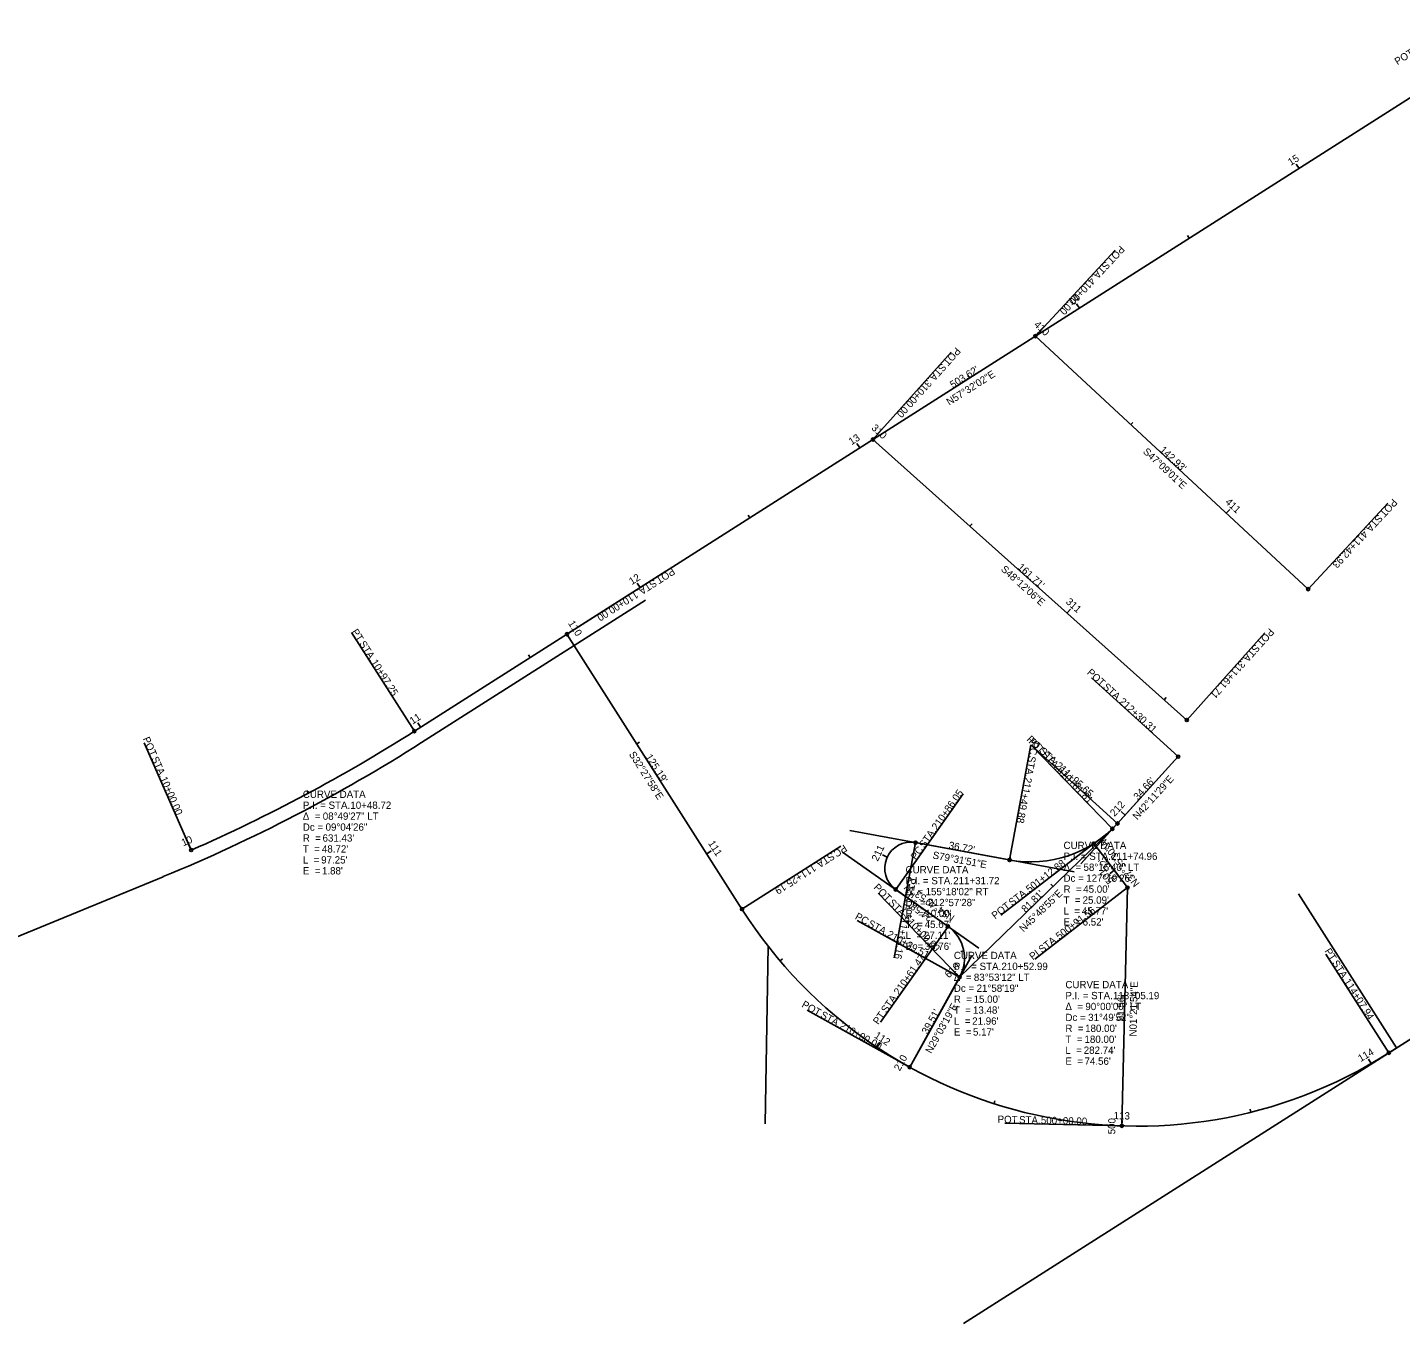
# Model space of a CAD drawing. Extents: x 143938 to 145591, y 512467 to 513276.
# Drawn here: x 144765 to 145292, y 512738 to 513236 of the extents above; entities that cross this region are included whole.
import ezdxf

# ---------------------------------------------------------------- set-up
doc = ezdxf.new("R2010")
doc.units = 0
for name, color, linetype in [('_CIVIL_CONSTRUCTION', 7, 'Continuous'), ('Default', 7, 'Continuous'), ('GE_P_Alignment', 7, 'Continuous'), ('GE_P_Alignment_100_Bearings', 7, 'Continuous'), ('GE_P_Alignment_100_Cardinal_Points', 7, 'Continuous'), ('GE_P_Alignment_100_Curve_Data', 7, 'Continuous'), ('GE_P_Alignment_100_Distances', 7, 'Continuous'), ('GE_P_Alignment_100_Stations', 7, 'Continuous'), ('GE_P_Driveway_CL', 7, 'Continuous'), ('SC_Scratch1', 7, 'Continuous')]:
    doc.layers.add(name, color=color, linetype=linetype)

msp = doc.modelspace()

# ---------------------------------------------------------------- linework, layer by layer
at = {"layer": '_CIVIL_CONSTRUCTION'}
for p, q in [((144915.99, 512961.08), (145002.01, 513015.81)), ((144609.55, 512824.24), (144816.71, 512909.56))]:
    msp.add_line(p, q, dxfattribs=at)
msp.add_arc((144574.25, 513498.21), 636.62, 292.38616, 302.46616, dxfattribs=at)
at = {"layer": 'Default'}
msp.add_line((145252.8, 512902.91), (145290.44, 512843.75), dxfattribs=at)
at = {"layer": 'GE_P_Alignment'}
for p, q in [((144913.21, 512965.47), (145338.11, 513235.81)), ((145151.72, 513117.22), (145256.51, 513020.01)), ((145089.33, 513077.52), (145209.88, 512969.74)), ((145124.06, 512737.89), (145591.23, 513035.12)), ((144971.8, 513002.75), (145039.01, 512897.12)), ((144971.8, 513002.75), (145039.01, 512897.12)), ((145183.29, 512930), (145206.56, 512955.68)), ((145122.64, 512870.94), (145181.31, 512927.96)), ((145105.66, 512922.65), (145141.77, 512915.97)), ((145105.66, 512922.65), (145141.77, 512915.97)), ((145187.13, 512905.37), (145174.13, 512922.26)), ((145287.5, 512841.88), (145396.48, 512911.21)), ((145118.17, 512890.48), (145098.08, 512904.64)), ((145118.17, 512890.48), (145098.08, 512904.64)), ((145184.95, 512813.83), (145187.13, 512905.37)), ((145103.45, 512836.4), (145122.64, 512870.94)), ((145103.45, 512836.4), (145122.64, 512870.94))]:
    msp.add_line(p, q, dxfattribs=at)
for centre, radius, start, end in [((144574.25, 513498.21), 631.43, 293.64203, 302.46616), ((144574.25, 513498.21), 631.43, 293.64203, 302.46616), ((145149.95, 512960.22), 45, 259.5308, 317.8085), ((145149.95, 512960.22), 45, 259.5308, 317.8085), ((145103.84, 512912.81), 10, 79.5308, 234.8313), ((145103.84, 512912.81), 10, 79.5308, 234.8313), ((145190.87, 512993.74), 180, 212.4662, 302.4662), ((145190.87, 512993.74), 180, 212.4662, 302.4662), ((145109.53, 512878.22), 15, 330.9446, 54.8313), ((145109.53, 512878.22), 15, 330.9446, 54.8313)]:
    msp.add_arc(centre, radius, start, end, dxfattribs=at)
at = {"layer": 'GE_P_Alignment_100_Cardinal_Points'}
for p, q in [((145151.72, 513117.22), (145182.33, 513150.21)), ((145089.33, 513077.52), (145119.32, 513111.07)), ((145256.51, 513020.01), (145287.12, 513053)), ((144971.8, 513002.75), (145009.77, 513026.9)), ((144913.21, 512965.47), (144889.05, 513003.43)), ((145209.88, 512969.74), (145239.88, 513003.29)), ((145206.56, 512955.68), (145173.22, 512985.9)), ((144827.47, 512919.78), (144809.42, 512961)), ((145141.77, 512915.97), (145149.95, 512960.22)), ((145183.29, 512930), (145149.95, 512960.22)), ((145181.31, 512927.96), (145149.95, 512960.22)), ((145098.08, 512904.64), (145124, 512941.42)), ((145039.01, 512897.12), (145076.97, 512921.28)), ((145105.66, 512922.65), (145097.48, 512878.4)), ((145174.13, 512922.26), (145138.47, 512894.81)), ((145187.13, 512905.37), (145151.47, 512877.92)), ((145122.64, 512870.94), (145091.28, 512903.21)), ((145122.64, 512870.94), (145083.31, 512892.79)), ((145118.17, 512890.48), (145092.25, 512853.7)), ((145287.5, 512841.88), (145263.34, 512879.84)), ((145103.45, 512836.4), (145064.12, 512858.25)), ((145184.95, 512813.83), (145139.96, 512814.91))]:
    msp.add_line(p, q, dxfattribs=at)
for centre in [(145151.72, 513117.22), (145089.33, 513077.52), (145256.51, 513020.01), (144971.8, 513002.75), (145209.88, 512969.74), (144913.21, 512965.47), (145206.56, 512955.68), (145183.29, 512930), (145181.31, 512927.96), (144827.47, 512919.78), (145105.66, 512922.65), (145174.13, 512922.26), (145141.77, 512915.97), (145098.08, 512904.64), (145187.13, 512905.37), (145039.01, 512897.12), (145118.17, 512890.48), (145122.64, 512870.94), (145122.64, 512870.94), (145287.5, 512841.88), (145103.45, 512836.4), (145184.95, 512813.83)]:
    msp.add_circle(centre, 0.6, dxfattribs=at)
at = {"layer": 'GE_P_Alignment_100_Stations'}
for p, q in [((145253.01, 513181.66), (145251.94, 513183.35)), ((145210.83, 513154.82), (145210.18, 513155.84)), ((145168.64, 513127.98), (145167.57, 513129.67)), ((145151.72, 513117.22), (145153.08, 513118.69)), ((145126.46, 513101.14), (145125.81, 513102.16)), ((145188.38, 513083.22), (145189.2, 513084.1)), ((145089.33, 513077.52), (145090.66, 513079.01)), ((145084.27, 513074.3), (145083.2, 513075.99)), ((145042.09, 513047.46), (145041.44, 513048.48)), ((145225.04, 513049.21), (145226.4, 513050.68)), ((145126.61, 513044.2), (145127.41, 513045.09)), ((144999.9, 513020.62), (144998.83, 513022.31)), ((145163.88, 513010.87), (145165.21, 513012.36)), ((144971.8, 513002.75), (144973.49, 513003.82)), ((144957.71, 512993.78), (144957.07, 512994.8)), ((145201.16, 512977.55), (145201.96, 512978.44)), ((144915.53, 512966.94), (144914.46, 512968.63)), ((144998.64, 512960.56), (144999.65, 512961.2)), ((144872.43, 512941.62), (144871.87, 512942.68)), ((145186.21, 512933.23), (145184.73, 512934.57)), ((144827.47, 512919.78), (144826.67, 512921.61)), ((145025.48, 512918.38), (145027.17, 512919.45)), ((145094.79, 512917.05), (145092.97, 512917.9)), ((145141.89, 512915.95), (145142.1, 512917.13)), ((145181.98, 512912.06), (145180.4, 512910.84)), ((145158.5, 512905.78), (145157.66, 512906.65)), ((145053.72, 512877.17), (145054.63, 512877.95)), ((145124.26, 512881.08), (145123.08, 512880.86)), ((145122.64, 512870.94), (145121.25, 512872.37)), ((145186.14, 512863.82), (145184.94, 512863.85)), ((145090.94, 512844.03), (145092.05, 512845.69)), ((145103.45, 512836.4), (145101.71, 512837.37)), ((145280.71, 512837.76), (145279.71, 512839.5)), ((145135.83, 512822.37), (145136.19, 512823.51)), ((145234.49, 512819.11), (145234.2, 512820.27)), ((145184.95, 512813.83), (145182.95, 512813.88)), ((145184.93, 512813.84), (145185, 512815.84))]:
    msp.add_line(p, q, dxfattribs=at)
at = {"layer": 'GE_P_Driveway_CL'}
for p, q in [((145252.8, 512902.91), (145290.44, 512843.75)), ((145049.03, 512882.93), (145047.91, 512814.66))]:
    msp.add_line(p, q, dxfattribs=at)
at = {"layer": 'SC_Scratch1'}
for p, q in [((145169.24, 512914.5), (145206.56, 512955.68)), ((145183.29, 512930), (145206.56, 512955.68)), ((145080.41, 512927.31), (145166.64, 512911.38)), ((145130.02, 512882.13), (145077.65, 512919.04)), ((145103.45, 512836.4), (145127.3, 512879.32))]:
    msp.add_line(p, q, dxfattribs=at)
for centre, radius, start, end in [((145149.95, 512960.22), 45, 259.5308, 317.8085), ((145103.84, 512912.81), 10, 79.5308, 234.8313), ((145109.53, 512878.22), 15, 330.9446, 54.8313)]:
    msp.add_arc(centre, radius, start, end, dxfattribs=at)

# ---------------------------------------------------------------- texts
at = {"layer": 'GE_P_Alignment_100_Bearings'}
for s, rotation, p in [('N57°32\'02"E', 32.4662, (145118.65, 513090.49)), ('S47°09\'01"E', 317.1504, (145192.83, 513072.54)), ('S48°12\'06"E', 318.2018, (145138.25, 513027.35)), ('S32°27\'58"E', 302.4662, (144995.48, 512956.58)), ('N42°11\'29"E', 47.8085, (145190.85, 512931.2)), ('N37°35\'30"W', 127.5916, (145191.95, 512906.98)), ('S79°31\'51"E', 349.5308, (145112.09, 512916.58)), ('N54°49\'53"W', 144.8313, (145120.96, 512894.39)), ('N45°48\'55"E', 44.1846, (145147.17, 512888.08)), ('N01°21\'54"E', 88.635, (145190.57, 512848.13)), ('N29°03\'19"E', 60.9446, (145111.73, 512841.4))]:
    msp.add_text(s, height=2.8, rotation=rotation, dxfattribs=at).set_placement(p)
at = {"layer": 'GE_P_Alignment_100_Cardinal_Points'}
for s, rotation, p in [('POT', 32.4662, (145290.8, 513221.26)), ('POT', 227.1504, (145184.26, 513152.23)), (' STA. ', 227.1504, (145179.36, 513146.96)), ('410+00.00', 227.1504, (145172.94, 513140.03)), ('POT', 228.2018, (145121.22, 513113.13)), (' STA. ', 228.2018, (145116.42, 513107.76)), ('310+00.00', 228.2018, (145110.12, 513100.72)), ('POT', 227.1504, (145289, 513054.97)), (' STA. ', 227.1504, (145284.1, 513049.69)), ('411+42.93', 227.1504, (145277.68, 513042.76)), ('POT', 212.4662, (145012.15, 513028.37)), (' STA. ', 212.4662, (145006.08, 513024.5)), ('110+00.00', 212.4662, (144998.1, 513019.43)), ('PT', 302.4662, (144888.95, 513003.66)), ('POT', 228.2018, (145241.64, 513005.2)), (' STA. ', 302.4662, (144891.32, 512999.94)), (' STA. ', 228.2018, (145236.84, 512999.84)), ('10+97.25', 302.4662, (144896.4, 512991.96)), ('POT', 317.8085, (145171.32, 512987.68)), ('311+61.71', 228.2018, (145230.54, 512992.79)), (' STA. ', 317.8085, (145176.66, 512982.85)), ('212+30.31', 317.8085, (145183.66, 512976.5)), ('POT', 293.642, (144808.79, 512962.56)), ('POT', 314.1846, (145148.16, 512962.12)), ('PT', 317.8085, (145148.96, 512961.17)), ('PC', 259.5308, (145150.26, 512961.67)), (' STA. ', 317.8085, (145152.23, 512958.21)), (' STA. ', 314.1846, (145153.18, 512956.96)), (' STA. ', 293.642, (144811.68, 512955.96)), (' STA. ', 259.5308, (145149.42, 512957.16)), ('211+95.65', 317.8085, (145159.24, 512951.86)), ('610+81.81', 314.1846, (145159.77, 512950.18)), ('10+00.00', 293.642, (144815.47, 512947.3)), ('211+49.88', 259.5308, (145147.71, 512947.87)), ('210+86.05', 54.8313, (145113.94, 512927.21)), (' STA. ', 54.8313, (145108.49, 512919.49)), ('PC', 212.4662, (145078.23, 512922.03)), ('PC', 54.8313, (145105.85, 512915.74)), ('111+25.19', 212.4662, (145066.39, 512914.49)), (' STA. ', 212.4662, (145074.36, 512919.56)), ('501+12.88', 37.5916, (145149.43, 512903.3)), ('PT', 259.5308, (145103.23, 512909.28)), ('POT', 314.1846, (145089.36, 512905.24)), (' STA. ', 259.5308, (145102.43, 512904.94)), (' STA. ', 37.5916, (145141.94, 512897.53)), (' STA. ', 314.1846, (145094.38, 512900.08)), ('POT', 37.5916, (145136.24, 512893.14)), ('PC', 330.9446, (145082.2, 512893.46)), ('211+13.16', 259.5308, (145100.71, 512895.65)), ('610+00.00', 314.1846, (145100.97, 512893.3)), ('500+91.56', 37.5916, (145160.91, 512885.23)), (' STA. ', 330.9446, (145086.2, 512891.23)), ('210+39.51', 330.9446, (145094.47, 512886.64)), (' STA. ', 37.5916, (145153.42, 512879.47)), ('210+61.47', 54.8313, (145099.36, 512863.85)), ('PI', 37.5916, (145150.73, 512877.4)), ('PT', 302.4662, (145262.66, 512880.99)), (' STA. ', 302.4662, (145265.03, 512877.26)), ('114+07.94', 302.4662, (145270.11, 512869.29)), ('POT', 330.9446, (145061.69, 512859.65)), (' STA. ', 54.8313, (145093.91, 512856.12)), (' STA. ', 330.9446, (145067.99, 512856.15)), ('PT', 54.8313, (145091.37, 512852.52)), ('210+00.00', 330.9446, (145076.25, 512851.56)), ('POT', 358.635, (145137.17, 512815.01)), (' STA. ', 358.635, (145144.37, 512814.84)), ('500+00.00', 358.635, (145153.81, 512814.62))]:
    msp.add_text(s, height=2.8, rotation=rotation, dxfattribs=at).set_placement(p)
at = {"layer": 'GE_P_Alignment_100_Curve_Data'}
for s, p in [('CURVE DATA', (144870.34, 512939.82)), ('P.I. = STA. ', (144870.34, 512935.62)), ('10+48.72', (144888.6, 512935.62)), ('Δ  = ', (144870.34, 512931.42)), ('Dc = ', (144870.34, 512927.22)), ('08°49\'27" LT', (144878.01, 512931.42)), ('09°04\'26"', (144879.08, 512927.22)), ('R  = ', (144870.34, 512923.02)), ("631.43'", (144877.92, 512923.02)), ('T  = ', (144870.34, 512918.82)), ("48.72'", (144877.68, 512918.82)), ('CURVE DATA', (145162.53, 512920.19)), ('L  = ', (144870.34, 512914.62)), ("97.25'", (144877.38, 512914.62)), ('Δ  = ', (145162.53, 512911.79)), ('P.I. = STA. ', (145162.53, 512915.99)), ('58°16\'40" LT', (145170.21, 512911.79)), ('211+74.96', (145180.8, 512915.99)), ('E  = ', (144870.34, 512910.42)), ("1.88'", (144877.68, 512910.42)), ('CURVE DATA', (145101.87, 512910.84)), ('P.I. = STA. ', (145101.87, 512906.64)), ('211+31.72', (145120.14, 512906.64)), ('Dc = ', (145162.53, 512907.59)), ('127°19\'26"', (145171.27, 512907.59)), ('Δ  = ', (145101.87, 512902.44)), ('155°18\'02" RT', (145109.55, 512902.44)), ('R  = ', (145162.53, 512903.39)), ("45.00'", (145170.11, 512903.39)), ('Dc = ', (145101.87, 512898.24)), ('212°57\'28"', (145110.61, 512898.24)), ('T  = ', (145162.53, 512899.19)), ("25.09'", (145169.87, 512899.19)), ('R  = ', (145101.87, 512894.04)), ("10.00'", (145109.45, 512894.04)), ('L  = ', (145162.53, 512894.99)), ('E  = ', (145162.53, 512890.79)), ("45.77'", (145169.57, 512894.99)), ("6.52'", (145169.87, 512890.79)), ('T  = ', (145101.87, 512889.84)), ('L  = ', (145101.87, 512885.64)), ("27.11'", (145108.91, 512885.64)), ("45.67'", (145109.21, 512889.84)), ('E  = ', (145101.87, 512881.44)), ("36.76'", (145109.21, 512881.44)), ('CURVE DATA', (145120.41, 512877.91)), ('Δ  = ', (145120.41, 512869.51)), ('P.I. = STA. ', (145120.41, 512873.71)), ('83°53\'12" LT', (145128.09, 512869.51)), ('210+52.99', (145138.68, 512873.71)), ('Dc = ', (145120.41, 512865.31)), ('21°58\'19"', (145129.15, 512865.31)), ('CURVE DATA', (145163.25, 512866.7)), ('R  = ', (145120.41, 512861.11)), ("15.00'", (145127.99, 512861.11)), ('P.I. = STA. ', (145163.25, 512862.5)), ('113+05.19', (145181.52, 512862.5)), ('T  = ', (145120.41, 512856.91)), ("13.48'", (145127.75, 512856.91)), ('Δ  = ', (145163.25, 512858.3)), ('Dc = ', (145163.25, 512854.1)), ('90°00\'00" LT', (145170.93, 512858.3)), ('31°49\'52"', (145171.99, 512854.1)), ('L  = ', (145120.41, 512852.71)), ('E  = ', (145120.41, 512848.51)), ("21.96'", (145127.45, 512852.71)), ("5.17'", (145127.75, 512848.51)), ('R  = ', (145163.25, 512849.9)), ("180.00'", (145170.83, 512849.9)), ('T  = ', (145163.25, 512845.7)), ("180.00'", (145170.59, 512845.7)), ('L  = ', (145163.25, 512841.5)), ("282.74'", (145170.29, 512841.5)), ('E  = ', (145163.25, 512837.3)), ("74.56'", (145170.59, 512837.3))]:
    msp.add_text(s, height=2.8, dxfattribs=at).set_placement(p)
at = {"layer": 'GE_P_Alignment_100_Distances'}
for s, rotation, p in [("503.62'", 32.4662, (145120, 513097.09)), ("142.93'", 317.1504, (145199.25, 513073.19)), ("161.71'", 318.2018, (145144.66, 513028.12)), ("125.19'", 302.4662, (145001.85, 512955.59)), ("34.66'", 47.8085, (145191.16, 512938.75)), ("36.72'", 349.5308, (145118.25, 512920.36)), ("21.32'", 127.5916, (145183.99, 512909.38)), ("81.81'", 44.1846, (145147.96, 512895.6)), ("24.58'", 144.8313, (145112.65, 512894.32)), ("91.56'", 88.635, (145185.87, 512854.04)), ("39.51'", 60.9446, (145110.31, 512848.82))]:
    msp.add_text(s, height=2.8, rotation=rotation, dxfattribs=at).set_placement(p)
at = {"layer": 'GE_P_Alignment_100_Stations'}
for s, rotation, p in [('15', 32.4662, (145249.82, 513182.6)), ('14', 32.4662, (145165.48, 513128.94)), ('410', 317.1504, (145150.97, 513121.33)), ('310', 318.2018, (145088.5, 513081.62)), ('13', 32.4662, (145081.11, 513075.26)), ('411', 317.1504, (145224.43, 513053.19)), ('12', 32.4662, (144996.73, 513021.57)), ('311', 318.2018, (145163.2, 513014.84)), ('110', 302.4662, (144972.11, 513006.91)), ('11', 32.4662, (144912.47, 512967.96)), ('212', 47.8085, (145182.15, 512932.48)), ('10', 23.642, (144824.43, 512921.17)), ('111', 302.4662, (145025.9, 512922.38)), ('211', 64.9071, (145091.19, 512915.26)), ('501', 127.5916, (145181.92, 512908.03)), ('610', 44.1846, (145118.5, 512870.4)), ('112', 326.2777, (145089.6, 512847.93)), ('210', 60.9446, (145099.64, 512834.68)), ('114', 29.9397, (145276.63, 512838.3)), ('113', 358.1087, (145181.74, 512816.45)), ('500', 88.635, (145182.37, 512810.55))]:
    msp.add_text(s, height=2.8, rotation=rotation, dxfattribs=at).set_placement(p)

doc.saveas('drawing.dxf')
